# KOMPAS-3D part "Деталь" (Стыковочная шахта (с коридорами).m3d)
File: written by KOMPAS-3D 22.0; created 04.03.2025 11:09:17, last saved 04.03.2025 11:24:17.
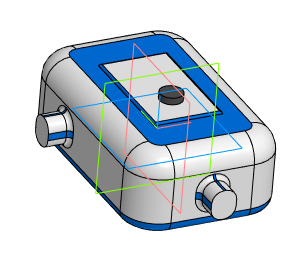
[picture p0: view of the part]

Document properties: Автор: Пользователь Windows; Полное имя файла: C:\Users\Student\Documents\Картошечка\База Сабнатика\Стыковочная шахта\Стыковочная шахта (с коридорами).m3d

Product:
- Body: Тело 1
    Масса: 1.418144
- Part/product: Деталь
    Масса: 1.451176

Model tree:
1. Эскиз:1
2. Элемент выдавливания:1
     Расстояние 1 = 35
3. Скругление:1  (with: Элемент выдавливания:1)
     Радиус = 15
4. Скругление:2  (with: Элемент выдавливания:1)
     Радиус = 10
5. Скругление:3  (with: Элемент выдавливания:1)
     Радиус = 5
6. Эскиз:2  (with: Элемент выдавливания:1)
7. Элемент выдавливания:2
     Расстояние 2 = 12
8. Эскиз:3  (with: Элемент выдавливания:1)
9. Элемент выдавливания:3
     Расстояние 1 = 1
10. Скругление:4  (with: Элемент выдавливания:3)
     Радиус = 1
11. Эскиз:4  (with: Элемент выдавливания:3)
12. Элемент выдавливания:4
     Расстояние 1 = 3
13. Эскиз:5  (with: Элемент выдавливания:1)
14. Элемент выдавливания:5
     Расстояние 1 = 10
15. Скругление:5  (with: Элемент выдавливания:5)
     Радиус = 2
16. Эскиз:6  (with: Элемент выдавливания:1)
17. Элемент выдавливания:6
     Расстояние 1 = 10
18. Скругление:6  (with: Элемент выдавливания:6)
     Радиус = 2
